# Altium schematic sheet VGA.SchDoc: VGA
size A4; Organization: Trenz Electronic GmbH / TT; DocumentNumber: TE0304 - Demo Baseboard; Revision: 00; SheetNumber: 4; SheetTotal: 4; Date: 2009-04-16
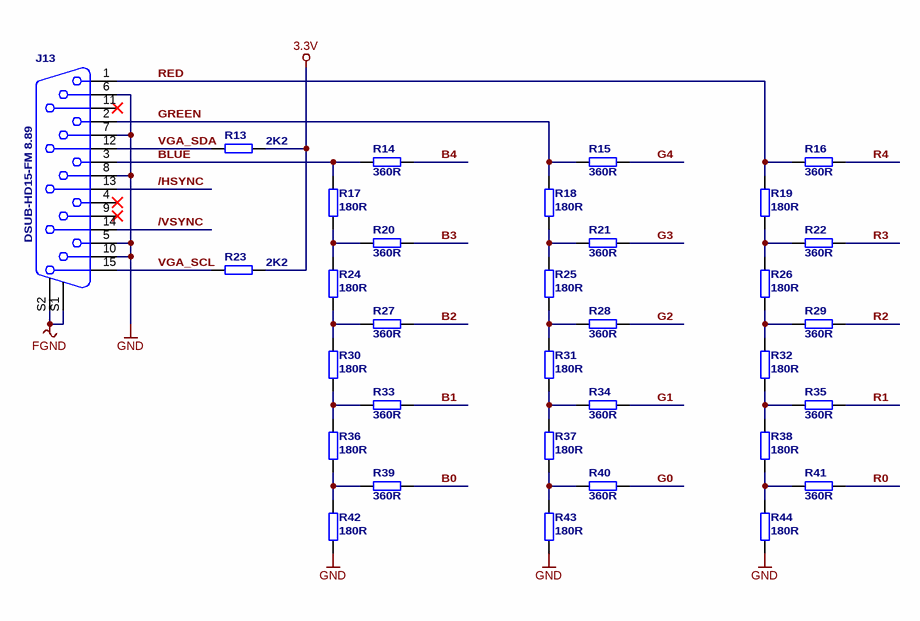
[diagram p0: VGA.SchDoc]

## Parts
J13  DSUB-HD15-FM 8.89  [WIESON 3110 F]
R13  2K2  [RESC1609N]
R14  360R  [RESC1609N]
R15  360R  [RESC1609N]
R16  360R  [RESC1609N]
R17  180R  [RESC1609N]
R18  180R  [RESC1609N]
R19  180R  [RESC1609N]
R20  360R  [RESC1609N]
R21  360R  [RESC1609N]
R22  360R  [RESC1609N]
R23  2K2  [RESC1609N]
R24  180R  [RESC1609N]
R25  180R  [RESC1609N]
R26  180R  [RESC1609N]
R27  360R  [RESC1609N]
R28  360R  [RESC1609N]
R29  360R  [RESC1609N]
R30  180R  [RESC1609N]
R31  180R  [RESC1609N]
R32  180R  [RESC1609N]
R33  360R  [RESC1609N]
R34  360R  [RESC1609N]
R35  360R  [RESC1609N]
R36  180R  [RESC1609N]
R37  180R  [RESC1609N]
R38  180R  [RESC1609N]
R39  360R  [RESC1609N]
R40  360R  [RESC1609N]
R41  360R  [RESC1609N]
R42  180R  [RESC1609N]
R43  180R  [RESC1609N]
R44  180R  [RESC1609N]

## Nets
3.3V: R13.2 R23.2
FGND: J13.S1 J13.S2
GND: J13.5 J13.6 J13.7 J13.8 J13.10 R42.2 R43.2 R44.2
/HSYNC: J13.13
/VSYNC: J13.14
B0: R39.2
B1: R33.2
B2: R27.2
B3: R20.2
B4: R14.2
BLUE: J13.3 R14.1 R17.1
G0: R40.2
G1: R34.2
G2: R28.2
G3: R21.2
G4: R15.2
GREEN: J13.2 R15.1 R18.1
R0: R41.2
R1: R35.2
R2: R29.2
R3: R22.2
R4: R16.2
RED: J13.1 R16.1 R19.1
VGA_SCL: J13.15 R23.1
VGA_SDA: J13.12 R13.1
NetR17_2: R17.2 R20.1 R24.1
NetR18_2: R18.2 R21.1 R25.1
NetR19_2: R19.2 R22.1 R26.1
NetR24_2: R24.2 R27.1 R30.1
NetR25_2: R25.2 R28.1 R31.1
NetR26_2: R26.2 R29.1 R32.1
NetR30_2: R30.2 R33.1 R36.1
NetR31_2: R31.2 R34.1 R37.1
NetR32_2: R32.2 R35.1 R38.1
NetR36_2: R36.2 R39.1 R42.1
NetR37_2: R37.2 R40.1 R43.1
NetR38_2: R38.2 R41.1 R44.1

Not connected (* = marked no-connect by the designer): J13 4* 9* 11*

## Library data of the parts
J13 = 21395: AN: 21395; Bezeichnung: STE DSUB 15pol Buchse 90° High Density
R13 R23 = 21377: AN: 21377; Bezeichnung: WID SMD 2K2 1% 0,1W; Value: 2.2K
R14-R16 R20-R22 R27-R29 R33-R35 R39-R41 = 22862: AN: 22862; Bezeichnung: WID SMD 360R 1% 0,1W; Value: 360
R17-R19 R24-R26 R30-R32 R36-R38 R42-R44 = 22860: AN: 22860; Bezeichnung: WID SMD 180R 1% 0,1W; Value: 180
